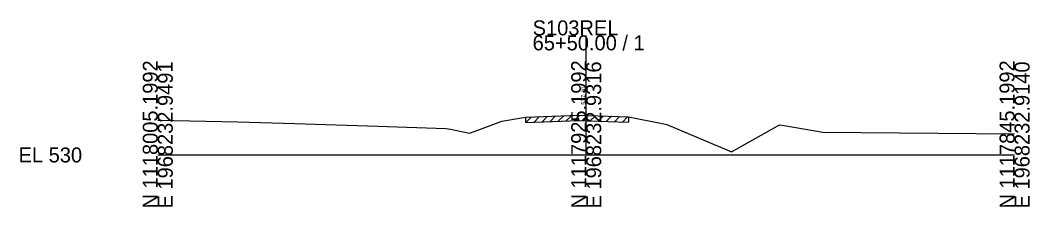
# Model space of a CAD drawing. Extents: x -26 to 163, y -10 to 24518.
# Drawn here: x -25.7 to 162.8, y 13990.3 to 14025.2 of the extents above; entities that cross this region are included whole.
import ezdxf

# ---------------------------------------------------------------- set-up
doc = ezdxf.new("R2010")
doc.units = 0
for name, color, linetype in [('RD_GPK_XS_Cell', 7, 'Continuous'), ('RD_XS_ExGround', 7, 'Continuous'), ('RD_XS_ExPaveRet', 7, 'Continuous'), ('RD_XS_TX_Elev_EX', 7, 'Continuous')]:
    doc.layers.add(name, color=color, linetype=linetype)

msp = doc.modelspace()

# ---------------------------------------------------------------- linework, layer by layer
at = {"layer": 'RD_GPK_XS_Cell'}
for p, q in [((80, 14000), (80, 14022.36)), ((0, 14000), (80, 14000)), ((80, 14000), (160, 14000))]:
    msp.add_line(p, q, dxfattribs=at)
at = {"layer": 'RD_XS_ExGround'}
msp.add_lwpolyline([(0, 14006.52), (14.92, 14006.18), (25.59, 14005.89), (41.07, 14005.38), (53.79, 14004.97), (54.65, 14004.8), (58.21, 14004.08), (59.25, 14004.47), (64.22, 14006.32), (67.94, 14006.93), (68.75, 14007.06), (70.43, 14007.13), (78.59, 14007.45), (80, 14007.4), (80.32, 14007.39), (87.91, 14007.12), (94.21, 14005.87), (95.08, 14005.68), (106.24, 14000.97), (107.11, 14000.59), (115.69, 14005.36), (116.15, 14005.62), (116.96, 14005.48), (124.18, 14004.24), (160, 14003.96)], dxfattribs=at)
at = {"layer": 'RD_XS_ExPaveRet'}
for p, q in [((68.75, 14006.06), (69.8, 14007.11)), ((68.75, 14006.06), (68.75, 14007.06)), ((68.75, 14006.06), (70.43, 14006.13)), ((70.26, 14006.13), (71.3, 14007.17)), ((70.43, 14006.13), (78.59, 14006.45)), ((71.76, 14006.19), (72.8, 14007.23)), ((73.26, 14006.24), (74.3, 14007.29)), ((74.76, 14006.3), (75.8, 14007.34)), ((76.26, 14006.36), (77.3, 14007.4)), ((77.76, 14006.42), (78.79, 14007.45)), ((78.59, 14006.45), (80, 14006.4)), ((79.26, 14006.43), (80.23, 14007.39)), ((80, 14006.4), (80.32, 14006.39)), ((80.32, 14006.39), (87.91, 14006.12)), ((80.76, 14006.37), (81.73, 14007.34)), ((82.26, 14006.32), (83.23, 14007.29)), ((83.76, 14006.27), (84.73, 14007.24)), ((85.27, 14006.22), (86.23, 14007.18)), ((86.77, 14006.16), (87.73, 14007.13)), ((87.91, 14007.12), (87.91, 14006.12))]:
    msp.add_line(p, q, dxfattribs=at)

# ---------------------------------------------------------------- texts
at = {"layer": 'RD_GPK_XS_Cell'}
for s, p in [('S103REL', (70, 14022.36)), ('65+50.00 / 1', (70, 14019.56)), ('EL 530', (-26, 13998.6))]:
    msp.add_text(s, height=2.8, dxfattribs=at).set_placement(p)
for s, p in [('N 1118005.1992', (0, 13990)), ('N 1117925.1992', (80, 13990)), ('N 1117845.1992', (160, 13990)), ('E 1968232.9491', (2.8, 13990)), ('E 1968232.9316', (82.8, 13990)), ('E 1968232.9140', (162.8, 13990))]:
    msp.add_text(s, height=2.8, rotation=90, dxfattribs=at).set_placement(p)
at = {"layer": 'RD_XS_TX_Elev_EX'}
msp.add_text('537.40', height=0.8, rotation=90, dxfattribs=at).set_placement((79.9, 14009.4))

doc.saveas('drawing.dxf')
